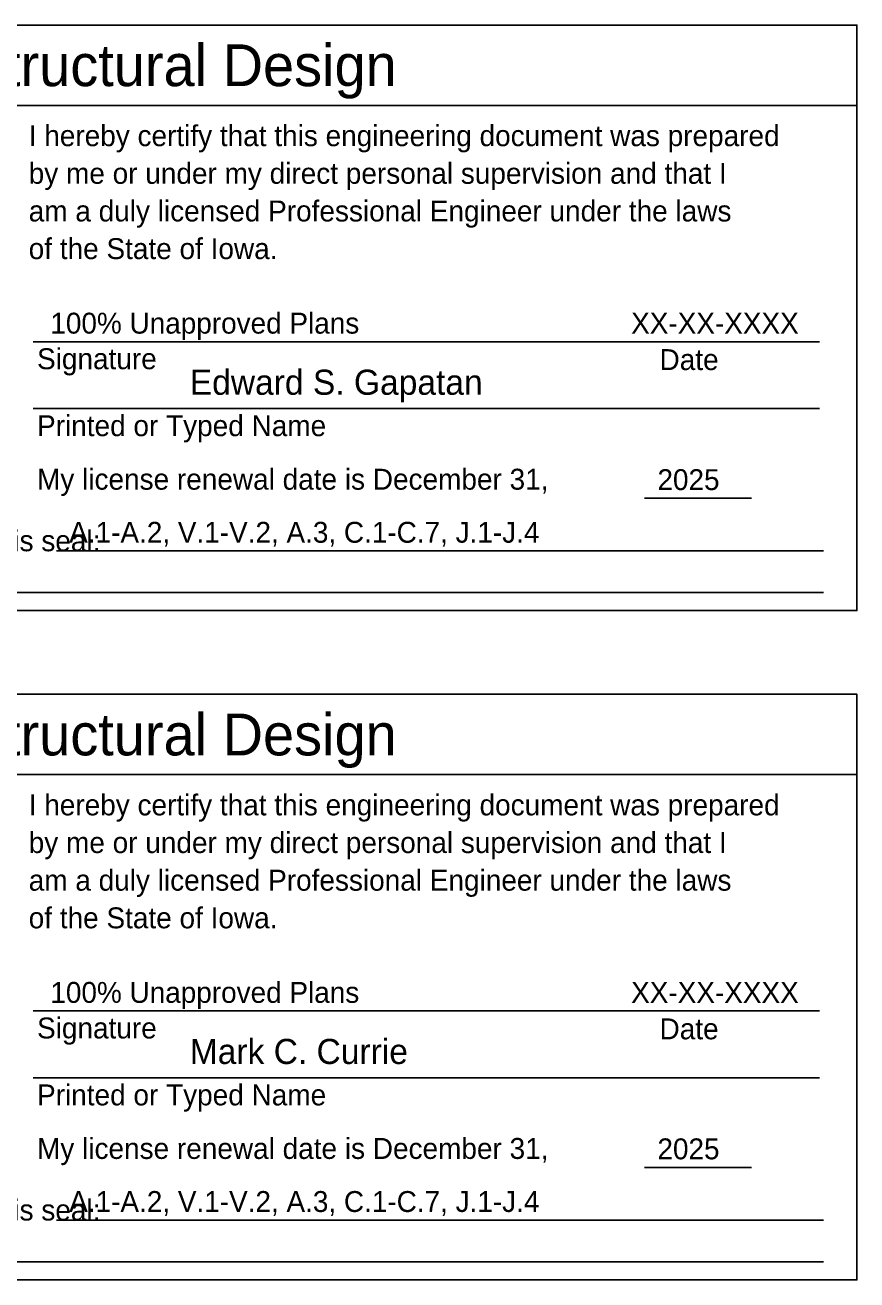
# Model space of a CAD drawing. Extents: x -0.84 to 4.97, y -1.01 to 2.42.
# Drawn here: x 3.19 to 3.605, y -0.986 to -0.361 of the extents above; entities that cross this region are included whole.
import ezdxf

# ---------------------------------------------------------------- set-up
doc = ezdxf.new("R2010")
doc.units = 0
for name, color, linetype in [('SheetGridMajor', 7, 'Continuous'), ('SheetGridMinor', 7, 'Continuous'), ('SheetText', 7, 'Continuous')]:
    doc.layers.add(name, color=color, linetype=linetype)

msp = doc.modelspace()

# ---------------------------------------------------------------- linework, layer by layer
at = {"layer": 'SheetGridMajor'}
for p, q in [((2.97968, -0.40149), (3.60468, -0.40149)), ((2.97968, -0.73482), (3.60468, -0.73482))]:
    msp.add_line(p, q, dxfattribs=at)
for points in [[(2.97968, -0.36149), (3.60468, -0.36149), (3.60468, -0.65315), (2.97968, -0.65315)], [(2.97968, -0.69482), (3.60468, -0.69482), (3.60468, -0.98649), (2.97968, -0.98649)]]:
    msp.add_lwpolyline(points, close=True, dxfattribs=at)
at = {"layer": 'SheetGridMinor'}
for p, q in [((3.58603, -0.51918), (3.19436, -0.51918)), ((3.58603, -0.55251), (3.19436, -0.55251)), ((3.55214, -0.59711), (3.49897, -0.59711)), ((3.206, -0.62335), (3.58802, -0.62335)), ((3.206, -0.62335), (3.58802, -0.62335)), ((2.9964, -0.64418), (3.58802, -0.64418)), ((3.58603, -0.85251), (3.19436, -0.85251)), ((3.58603, -0.88585), (3.19436, -0.88585)), ((3.55214, -0.93045), (3.49897, -0.93045)), ((3.206, -0.95668), (3.58802, -0.95668)), ((3.206, -0.95668), (3.58802, -0.95668)), ((2.9964, -0.97751), (3.58802, -0.97751))]:
    msp.add_line(p, q, dxfattribs=at)

# ---------------------------------------------------------------- texts
at = {"layer": 'SheetText'}
for s, height, p in [('Structural Design', 0.0208333, (3.16182, -0.3919)), ('I hereby certify that this engineering document was prepared', 0.0104167, (3.1922, -0.42179)), ('by me or under my direct personal supervision and that I', 0.0104167, (3.1922, -0.44054)), ('am a duly licensed Professional Engineer under the laws', 0.0104167, (3.1922, -0.45929)), ('of the State of Iowa.', 0.0104167, (3.1922, -0.47804)), ('100% Unapproved Plans', 0.0104, (3.20298, -0.51515)), ('XX-XX-XXXX', 0.0104, (3.49224, -0.51515)), ('Signature', 0.010417, (3.19635, -0.53289)), ('Date', 0.010417, (3.50639, -0.53331)), ('Edward S. Gapatan', 0.0125, (3.27242, -0.54562)), ('Printed or Typed Name', 0.0104167, (3.19635, -0.56623)), ('My license renewal date is December 31,', 0.0104167, (3.19635, -0.59289)), ('2025', 0.0104, (3.50534, -0.59309)), ('A.1-A.2, V.1-V.2, A.3, C.1-C.7, J.1-J.4', 0.0104, (3.21237, -0.61932)), ('Pages or sheets covered by this seal:', 0.0104167, (2.9964, -0.62355)), ('Structural Design', 0.0208333, (3.16182, -0.72524)), ('I hereby certify that this engineering document was prepared', 0.0104167, (3.1922, -0.75512)), ('by me or under my direct personal supervision and that I', 0.0104167, (3.1922, -0.77387)), ('am a duly licensed Professional Engineer under the laws', 0.0104167, (3.1922, -0.79262)), ('of the State of Iowa.', 0.0104167, (3.1922, -0.81137)), ('100% Unapproved Plans', 0.0104, (3.20298, -0.84849)), ('XX-XX-XXXX', 0.0104, (3.49224, -0.84849)), ('Signature', 0.010417, (3.19635, -0.86623)), ('Date', 0.010417, (3.50639, -0.86665)), ('Mark C. Currie', 0.0125, (3.27242, -0.87895)), ('Printed or Typed Name', 0.0104167, (3.19635, -0.89956)), ('My license renewal date is December 31,', 0.0104167, (3.19635, -0.92623)), ('2025', 0.0104, (3.50534, -0.92642)), ('A.1-A.2, V.1-V.2, A.3, C.1-C.7, J.1-J.4', 0.0104, (3.21237, -0.95265)), ('Pages or sheets covered by this seal:', 0.0104167, (2.9964, -0.95689))]:
    msp.add_text(s, height=height, dxfattribs=at).set_placement(p)

doc.saveas('drawing.dxf')
